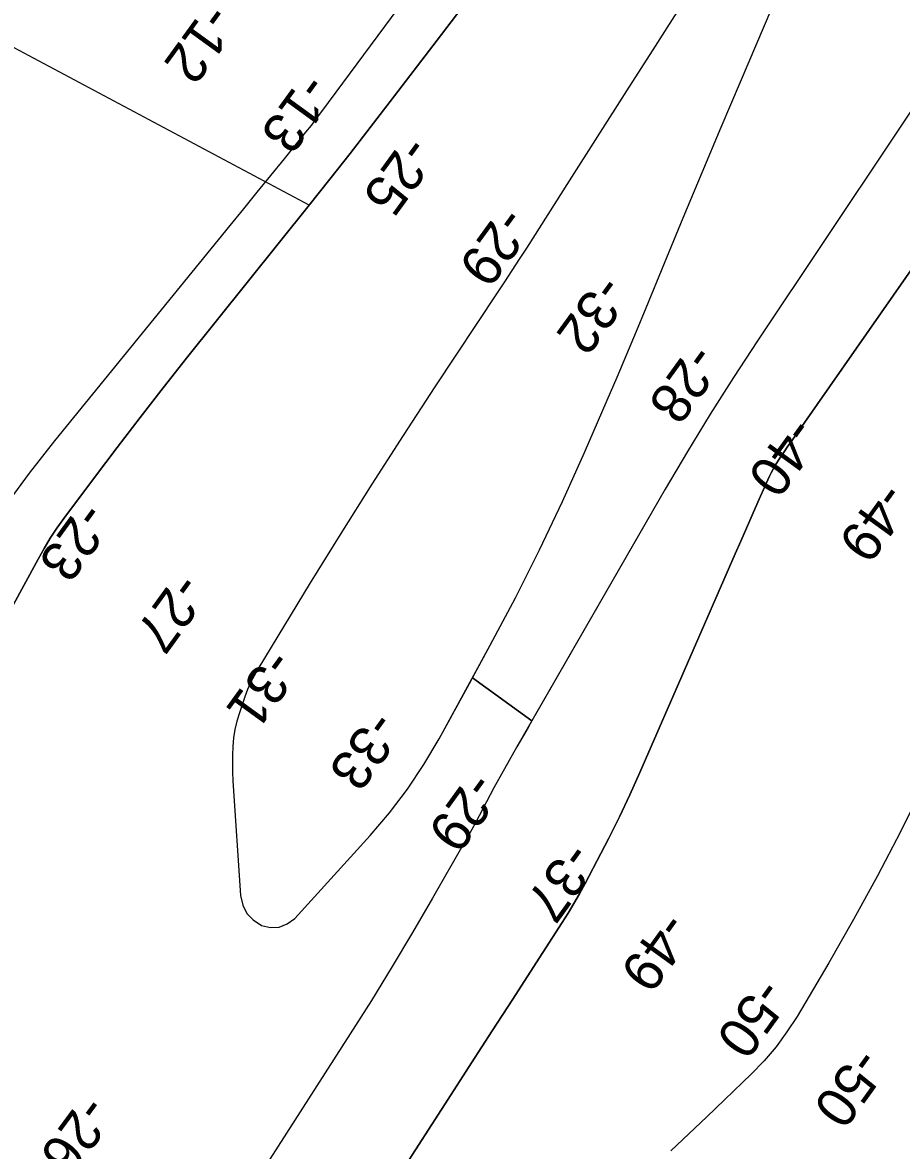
# Model space of a CAD drawing. Extents: x 3879599 to 3900814, y 146526 to 168888.
# Drawn here: x 3894343 to 3895080, y 160771 to 161718 of the extents above; entities that cross this region are included whole.
import ezdxf

# ---------------------------------------------------------------- set-up
doc = ezdxf.new("R2010")
doc.units = 0
for name, color, linetype in [('V-RIVR-RANG', 7, 'Continuous'), ('V-TOPO-DPTH', 7, 'Continuous'), ('V-TOPO-MAJR', 7, 'Continuous'), ('V-TOPO-MINR', 7, 'Continuous')]:
    doc.layers.add(name, color=color, linetype=linetype)

msp = doc.modelspace()

# ---------------------------------------------------------------- linework, layer by layer
at = {"layer": 'V-TOPO-DPTH'}
for points in [[(3894583.39, 161564.9), (3894255.7, 161739.59), (3894330.09, 161816.04), (3894779.1, 162471.69), (3894959.67, 162614.35), (3894982.55, 162633.86), (3895004.38, 162654.41), (3895024.63, 162676.51), (3895043.83, 162699.66), (3895072.99, 162737.61), (3895076.66, 162742.66), (3895080.14, 162747.83), (3895083.35, 162753.17), (3895086.37, 162758.63), (3895101.79, 162788.37), (3895104.27, 162794.7), (3895105.86, 162801.16), (3895106.1, 162807.8), (3895105.44, 162814.57), (3895407.09, 162684.23)], [(3895084.31, 162250.64), (3895077.08, 162241.29), (3895070.01, 162231.8), (3895031.35, 162178.54), (3895005.23, 162142.21), (3894979.33, 162105.74), (3894953.74, 162069.04), (3894928.36, 162032.2), (3894876.13, 161955.66), (3894866.19, 161941.25), (3894856.17, 161926.91), (3894846.01, 161912.66), (3894835.76, 161898.48), (3894801.73, 161851.87), (3894774.27, 161814.52), (3894746.65, 161777.29), (3894718.78, 161740.25), (3894690.75, 161703.33), (3894651.28, 161651.69), (3894634.47, 161629.86), (3894617.57, 161608.11), (3894600.53, 161586.47), (3894583.39, 161564.9)], [(3894770.14, 161131.82), (3894720.32, 161168.03), (3894735.27, 161195.39), (3894756.31, 161235.18), (3894776.61, 161275.32), (3894795.81, 161316), (3894814.28, 161357.04), (3894833.42, 161401.18), (3894841.71, 161420.44), (3894849.91, 161439.74), (3894858.01, 161459.08), (3894866.02, 161478.46), (3894881.42, 161516.02), (3894897.16, 161554.17), (3894913, 161592.28), (3894928.99, 161630.32), (3894945.1, 161668.32), (3894991.18, 161776.42), (3895000, 161796.79), (3895008.96, 161817.09)], [(3894897.57, 161736.06), (3894873.53, 161698.37), (3894849.5, 161660.67), (3894825.47, 161622.96), (3894801.46, 161585.25), (3894765.53, 161528.79), (3894759.46, 161519.32), (3894753.36, 161509.87), (3894747.21, 161500.45), (3894741.03, 161491.05), (3894688.87, 161412.31), (3894662.17, 161371.49), (3894635.78, 161330.48), (3894609.87, 161289.16), (3894584.27, 161247.65), (3894540.29, 161175.4), (3894537.11, 161169.77), (3894534.19, 161164.02), (3894531.65, 161158.1), (3894529.36, 161152.05), (3894524.73, 161138.48), (3894522.69, 161131.57), (3894521.03, 161124.59), (3894519.94, 161117.5), (3894519.23, 161110.33), (3894518.95, 161103.11), (3894518.85, 161095.89), (3894519.02, 161088.67), (3894519.37, 161081.45), (3894525.8, 160985.19), (3894527.72, 160977.26), (3894531.03, 160970.29), (3894536.41, 160964.76), (3894543.18, 160960.2), (3894550.87, 160958.47), (3894558.19, 160958.56), (3894564.94, 160961.4), (3894571.31, 160966.06), (3894634.56, 161035.64), (3894650.67, 161054.7), (3894665.82, 161074.44), (3894679.52, 161095.2), (3894692.26, 161116.66), (3894735.27, 161195.39), (3894756.31, 161235.18), (3894776.61, 161275.32), (3894795.81, 161316), (3894814.28, 161357.04), (3894833.42, 161401.18), (3894841.71, 161420.44), (3894849.91, 161439.74), (3894858.01, 161459.08), (3894866.02, 161478.46), (3894881.42, 161516.02), (3894897.16, 161554.17), (3894913, 161592.28), (3894928.99, 161630.32), (3894945.1, 161668.32), (3894991.18, 161776.42)], [(3894333.64, 161226.39), (3894355.85, 161267.74), (3894360.83, 161276.53), (3894366.06, 161285.17), (3894371.67, 161293.57), (3894377.53, 161301.81), (3894403.18, 161336.25), (3894422.19, 161361.48), (3894441.37, 161386.58), (3894460.81, 161411.49), (3894480.42, 161436.25), (3894583.39, 161564.9), (3894600.53, 161586.47), (3894617.57, 161608.11), (3894634.47, 161629.86), (3894651.28, 161651.69), (3894690.75, 161703.33), (3894718.78, 161740.25)], [(3894897.57, 161736.06), (3894873.53, 161698.37), (3894849.5, 161660.67), (3894825.47, 161622.96), (3894801.46, 161585.25), (3894765.53, 161528.79), (3894759.46, 161519.32), (3894753.36, 161509.87), (3894747.21, 161500.45), (3894741.03, 161491.05), (3894688.87, 161412.31), (3894662.17, 161371.49), (3894635.78, 161330.48), (3894609.87, 161289.16), (3894584.27, 161247.65), (3894540.29, 161175.4), (3894537.11, 161169.77), (3894534.19, 161164.02), (3894531.65, 161158.1), (3894529.36, 161152.05), (3894524.73, 161138.48), (3894522.69, 161131.57), (3894521.03, 161124.59), (3894519.94, 161117.5), (3894519.23, 161110.33), (3894518.95, 161103.11), (3894518.85, 161095.89), (3894519.02, 161088.67), (3894519.37, 161081.45), (3894525.8, 160985.19), (3894527.72, 160977.26), (3894531.03, 160970.29), (3894536.41, 160964.76), (3894543.18, 160960.2), (3894550.87, 160958.47), (3894558.19, 160958.56), (3894564.94, 160961.4), (3894571.31, 160966.06), (3894634.56, 161035.64), (3894650.67, 161054.7), (3894665.82, 161074.44), (3894679.52, 161095.2), (3894692.26, 161116.66), (3894717.71, 161163.25), (3894720.32, 161168.03), (3894770.14, 161131.82), (3894767.05, 161126.43)], [(3895130.91, 161707.79), (3894959.41, 161450.91), (3894939.36, 161420.22), (3894919.72, 161389.26), (3894900.7, 161357.93), (3894882.1, 161326.33), (3894757.64, 161110.08), (3894751.13, 161098.63), (3894744.7, 161087.14), (3894738.39, 161075.58), (3894732.16, 161063.97), (3894725.85, 161052.06), (3894722.81, 161046.39), (3894719.74, 161040.74), (3894716.61, 161035.12), (3894713.44, 161029.53), (3894686.75, 160982.93), (3894670, 160954.17), (3894652.97, 160925.59), (3894635.51, 160897.26), (3894617.77, 160869.11), (3894529.4, 160731.2)], [(3895130.91, 161707.79), (3894959.41, 161450.91), (3894939.36, 161420.22), (3894919.72, 161389.26), (3894900.7, 161357.93), (3894882.1, 161326.33), (3894770.14, 161131.82)], [(3894610.13, 160674.92), (3894702.44, 160818.19), (3894719.65, 160844.88), (3894736.86, 160871.57), (3894754.07, 160898.25), (3894771.29, 160924.93), (3894795.57, 160962.53), (3894800.55, 160970.47), (3894805.4, 160978.49), (3894810.03, 160986.63), (3894814.53, 160994.85), (3894825.01, 161014.6), (3894834.43, 161032.87), (3894843.57, 161051.27), (3894852.28, 161069.87), (3894860.72, 161088.61), (3894940.76, 161271.96), (3894945.52, 161282.85), (3894950.28, 161293.75), (3894955.06, 161304.64), (3894959.84, 161315.52), (3894966.74, 161331.2), (3894968.12, 161334.23), (3894969.54, 161337.23), (3894971.05, 161340.19), (3894972.6, 161343.13), (3894974.31, 161346.26), (3894975.07, 161347.6), (3894977.54, 161351.52), (3894980.12, 161355.29), (3894982.3, 161358.45), (3894984.48, 161361.61), (3894986.66, 161364.76), (3894988.85, 161367.9), (3895158.47, 161610.62)], [(3894610.13, 160674.92), (3894702.44, 160818.19), (3894719.65, 160844.88), (3894736.86, 160871.57), (3894754.07, 160898.25), (3894771.29, 160924.93), (3894795.57, 160962.53), (3894800.55, 160970.47), (3894805.4, 160978.49), (3894810.03, 160986.63), (3894814.53, 160994.85), (3894825.01, 161014.6), (3894834.43, 161032.87), (3894843.57, 161051.27), (3894852.28, 161069.87), (3894860.72, 161088.61), (3894940.76, 161271.96), (3894945.52, 161282.85), (3894950.28, 161293.75), (3894955.06, 161304.64), (3894959.84, 161315.52), (3894966.74, 161331.2), (3894968.12, 161334.23), (3894969.54, 161337.23), (3894971.05, 161340.19), (3894972.6, 161343.13), (3894974.31, 161346.26), (3894975.07, 161347.6), (3894977.54, 161351.52), (3894980.12, 161355.29), (3894982.3, 161358.45), (3894984.48, 161361.61), (3894986.66, 161364.76), (3894988.85, 161367.9), (3895158.47, 161610.62)], [(3894767.05, 161126.43), (3894757.64, 161110.08), (3894751.13, 161098.63), (3894744.7, 161087.14), (3894738.39, 161075.58), (3894732.16, 161063.97), (3894725.85, 161052.06), (3894722.81, 161046.39), (3894719.74, 161040.74), (3894716.61, 161035.12), (3894713.44, 161029.53), (3894686.75, 160982.93), (3894670, 160954.17), (3894652.97, 160925.59), (3894635.51, 160897.26), (3894617.77, 160869.11), (3894529.4, 160731.2)]]:
    msp.add_lwpolyline(points, dxfattribs=at)
at = {"layer": 'V-TOPO-MAJR'}
msp.add_lwpolyline([(3895097.82, 161076.34), (3895079.39, 161038.83), (3895060.29, 161001.69), (3895040.16, 160965.08), (3895019.35, 160928.84), (3894992.65, 160883.76), (3894984.18, 160870.73), (3894975.06, 160858.21), (3894964.95, 160846.48), (3894954.18, 160835.27), (3894946.8, 160828.18), (3894931.83, 160813.83), (3894916.85, 160799.5), (3894901.85, 160785.17), (3894886.84, 160770.86)], dxfattribs=at)
at = {"layer": 'V-TOPO-MINR'}
for points in [[(3894699.42, 161786.31), (3894593.7, 161643.39), (3894589.31, 161637.55), (3894584.88, 161631.75), (3894580.36, 161626.01), (3894575.79, 161620.31), (3894562.25, 161603.66), (3894550.87, 161589.67), (3894539.48, 161575.68), (3894528.1, 161561.69), (3894516.72, 161547.71), (3894369.54, 161366.85), (3894348.48, 161339.93), (3894328.12, 161312.5)], [(3894897.57, 161736.06), (3894873.53, 161698.37), (3894849.5, 161660.67), (3894825.47, 161622.96), (3894801.46, 161585.25), (3894765.53, 161528.79), (3894759.46, 161519.32), (3894753.36, 161509.87), (3894747.21, 161500.45), (3894741.03, 161491.05), (3894688.87, 161412.31), (3894662.17, 161371.49), (3894635.78, 161330.48), (3894609.87, 161289.16), (3894584.27, 161247.65), (3894540.29, 161175.4), (3894537.11, 161169.77), (3894534.19, 161164.02), (3894531.65, 161158.1), (3894529.36, 161152.05), (3894524.73, 161138.48), (3894522.69, 161131.57), (3894521.03, 161124.59), (3894519.94, 161117.5), (3894519.23, 161110.33), (3894518.95, 161103.11), (3894518.85, 161095.89), (3894519.02, 161088.67), (3894519.37, 161081.45), (3894525.8, 160985.19), (3894527.72, 160977.26), (3894531.03, 160970.29), (3894536.41, 160964.76), (3894543.18, 160960.2), (3894550.87, 160958.47), (3894558.19, 160958.56), (3894564.94, 160961.4), (3894571.31, 160966.06), (3894634.56, 161035.64), (3894650.67, 161054.7), (3894665.82, 161074.44), (3894679.52, 161095.2), (3894692.26, 161116.66), (3894735.27, 161195.39), (3894756.31, 161235.18), (3894776.61, 161275.32), (3894795.81, 161316), (3894814.28, 161357.04), (3894833.42, 161401.18), (3894841.71, 161420.44), (3894849.91, 161439.74), (3894858.01, 161459.08), (3894866.02, 161478.46), (3894881.42, 161516.02), (3894897.16, 161554.17), (3894913, 161592.28), (3894928.99, 161630.32), (3894945.1, 161668.32), (3894991.18, 161776.42)], [(3894718.78, 161740.25), (3894690.75, 161703.33), (3894651.28, 161651.69), (3894634.47, 161629.86), (3894617.57, 161608.11), (3894600.53, 161586.47), (3894583.39, 161564.9), (3894480.42, 161436.25), (3894460.81, 161411.49), (3894441.37, 161386.58), (3894422.19, 161361.48), (3894403.18, 161336.25), (3894377.53, 161301.81), (3894371.67, 161293.57), (3894366.06, 161285.17), (3894360.83, 161276.53), (3894355.85, 161267.74), (3894333.64, 161226.39)], [(3895130.91, 161707.79), (3894959.41, 161450.91), (3894939.36, 161420.22), (3894919.72, 161389.26), (3894900.7, 161357.93), (3894882.1, 161326.33), (3894757.64, 161110.08), (3894751.13, 161098.63), (3894744.7, 161087.14), (3894738.39, 161075.58), (3894732.16, 161063.97), (3894725.85, 161052.06), (3894722.81, 161046.39), (3894719.74, 161040.74), (3894716.61, 161035.12), (3894713.44, 161029.53), (3894686.75, 160982.93), (3894670, 160954.17), (3894652.97, 160925.59), (3894635.51, 160897.26), (3894617.77, 160869.11), (3894529.4, 160731.2)], [(3895158.47, 161610.62), (3894988.85, 161367.9), (3894986.66, 161364.76), (3894984.48, 161361.61), (3894982.3, 161358.45), (3894980.12, 161355.29), (3894977.54, 161351.52), (3894975.07, 161347.6), (3894974.31, 161346.26), (3894972.6, 161343.13), (3894971.05, 161340.19), (3894969.54, 161337.23), (3894968.12, 161334.23), (3894966.74, 161331.2), (3894959.84, 161315.52), (3894955.06, 161304.64), (3894950.28, 161293.75), (3894945.52, 161282.85), (3894940.76, 161271.96), (3894860.72, 161088.61), (3894852.28, 161069.87), (3894843.57, 161051.27), (3894834.43, 161032.87), (3894825.01, 161014.6), (3894814.53, 160994.85), (3894810.03, 160986.63), (3894805.4, 160978.49), (3894800.55, 160970.47), (3894795.57, 160962.53), (3894771.29, 160924.93), (3894754.07, 160898.25), (3894736.86, 160871.57), (3894719.65, 160844.88), (3894702.44, 160818.19), (3894610.13, 160674.92)]]:
    msp.add_lwpolyline(points, dxfattribs=at)

# ---------------------------------------------------------------- texts
at = {"layer": 'V-RIVR-RANG'}
for s, rotation, p in [('-12', 233.97833, (3894498.37, 161735.87)), ('-13', 233.97833, (3894579.55, 161677.48)), ('-25', 233.97833, (3894665.08, 161625.06)), ('-29', 233.97833, (3894745.56, 161565.7)), ('-32', 233.97833, (3894827.59, 161508.48)), ('-28', 234.12103, (3894904.66, 161450.51)), ('-40', 234.12103, (3894987.91, 161389.05)), ('-49', 234.12103, (3895064.13, 161334.17)), ('-23', 234.05833, (3894393.14, 161317.84)), ('-27', 234.05833, (3894473.31, 161258.06)), ('-31', 234.05833, (3894550.47, 161194.12)), ('-33', 234.05833, (3894636.6, 161142.56)), ('-29', 234.19797, (3894719.62, 161091.03)), ('-37', 234.19797, (3894800.79, 161032.11)), ('-49', 234.19797, (3894880.98, 160973.54)), ('-50', 234.19797, (3894961.51, 160917.83)), ('-50', 234.19797, (3895042.97, 160859.49)), ('-26', 233.67833, (3894394.58, 160819.71))]:
    msp.add_text(s, height=33.5, rotation=rotation, dxfattribs=at).set_placement(p)

doc.saveas('drawing.dxf')
